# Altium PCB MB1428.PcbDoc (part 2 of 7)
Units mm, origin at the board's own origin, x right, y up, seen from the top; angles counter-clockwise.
Board outline 55.88 x 152.4 mm, 4 copper layers (Top Layer, Signal Layer 1, Signal Layer 2, Bottom Layer), stack 1.614 mm thick; 396 components, 227 nets, 1346 pads, 1469 vias.
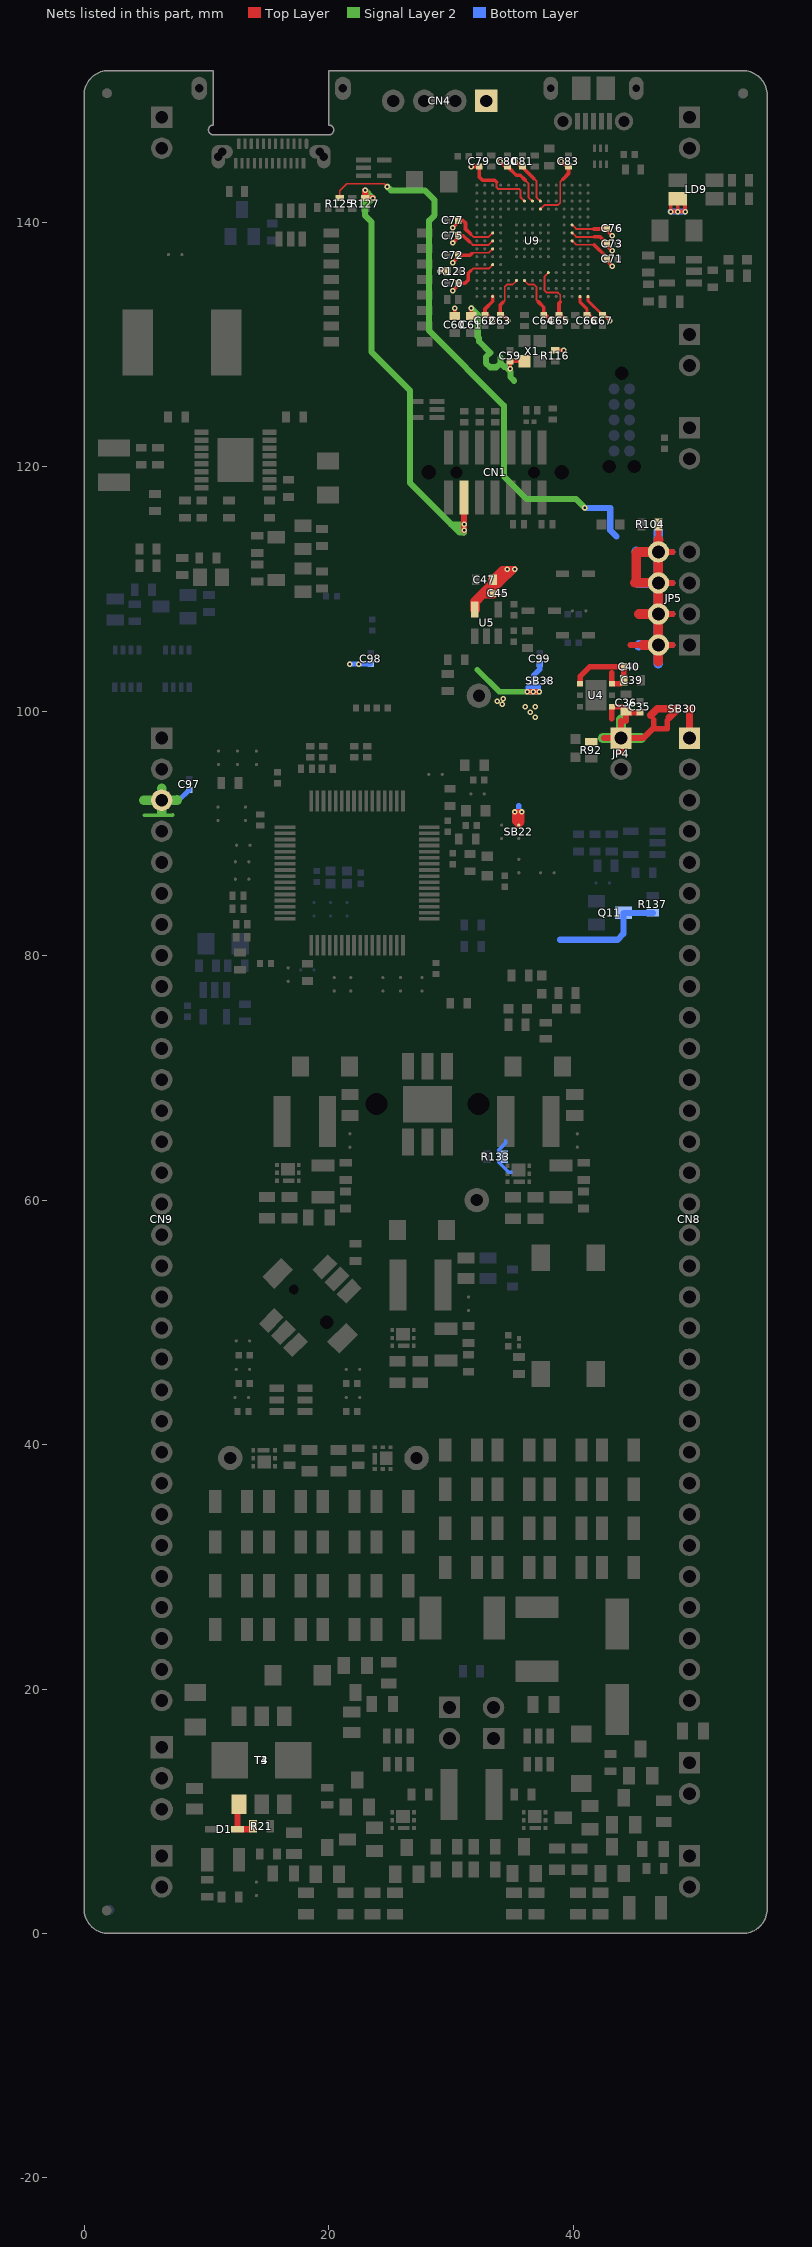
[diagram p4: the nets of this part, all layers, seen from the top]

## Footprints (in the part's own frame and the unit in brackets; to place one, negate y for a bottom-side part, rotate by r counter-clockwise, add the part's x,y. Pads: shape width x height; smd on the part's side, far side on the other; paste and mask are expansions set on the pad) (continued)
ICC_UFBGA201_176+25_10X10_P065 [mm] "IPC"
  round 0.25 smd mask+0.05: A1(-4.55,4.55) A2(-3.9,4.55) A3(-3.25,4.55) A4(-2.6,4.55) A5(-1.95,4.55) A6(-1.3,4.55) A7(-0.65,4.55) A8(0,4.55) A9(0.65,4.55) A10(1.3,4.55) A11(1.95,4.55) A12(2.6,4.55) A13(3.25,4.55) A14(3.9,4.55) A15(4.55,4.55) B1(-4.55,3.9) B2(-3.9,3.9) B3(-3.25,3.9) B4(-2.6,3.9) B5(-1.95,3.9) B6(-1.3,3.9) B7(-0.65,3.9) B8(0,3.9) B9(0.65,3.9) B10(1.3,3.9) B11(1.95,3.9) B12(2.6,3.9) B13(3.25,3.9) B14(3.9,3.9) B15(4.55,3.9) C1(-4.55,3.25) C2(-3.9,3.25) C3(-3.25,3.25) C4(-2.6,3.25) C5(-1.95,3.25) C6(-1.3,3.25) C7(-0.65,3.25) C8(0,3.25) C9(0.65,3.25) C10(1.3,3.25) C11(1.95,3.25) C12(2.6,3.25) C13(3.25,3.25) C14(3.9,3.25) C15(4.55,3.25) D1(-4.55,2.6) D2(-3.9,2.6) D3(-3.25,2.6) D4(-2.6,2.6) D5(-1.95,2.6) D6(-1.3,2.6) D7(-0.65,2.6) D8(0,2.6) D9(0.65,2.6) D10(1.3,2.6) D11(1.95,2.6) D12(2.6,2.6) D13(3.25,2.6) D14(3.9,2.6) D15(4.55,2.6) E1(-4.55,1.95) E2(-3.9,1.95) E3(-3.25,1.95) E4(-2.6,1.95) E12(2.6,1.95) E13(3.25,1.95) E14(3.9,1.95) E15(4.55,1.95) F1(-4.55,1.3) F2(-3.9,1.3) F3(-3.25,1.3) F4(-2.6,1.3) F6(-1.3,1.3) F7(-0.65,1.3) F8(0,1.3) F9(0.65,1.3) F10(1.3,1.3) F12(2.6,1.3) F13(3.25,1.3) F14(3.9,1.3) F15(4.55,1.3) G1(-4.55,0.65) G2(-3.9,0.65) G3(-3.25,0.65) G4(-2.6,0.65) G6(-1.3,0.65) G7(-0.65,0.65) G8(0,0.65) G9(0.65,0.65) G10(1.3,0.65) G12(2.6,0.65) G13(3.25,0.65) G14(3.9,0.65) G15(4.55,0.65) H1(-4.55,0) H2(-3.9,0) H3(-3.25,0) H4(-2.6,0) H6(-1.3,0) H7(-0.65,0) H8(0,0) H9(0.65,0) H10(1.3,0) H12(2.6,0) H13(3.25,0) H14(3.9,0) H15(4.55,0) J1(-4.55,-0.65) J2(-3.9,-0.65) J3(-3.25,-0.65) J4(-2.6,-0.65) J6(-1.3,-0.65) J7(-0.65,-0.65) J8(0,-0.65) J9(0.65,-0.65) J10(1.3,-0.65) J12(2.6,-0.65) J13(3.25,-0.65) J14(3.9,-0.65) J15(4.55,-0.65) K1(-4.55,-1.3) K2(-3.9,-1.3) K3(-3.25,-1.3) K4(-2.6,-1.3) K6(-1.3,-1.3) K7(-0.65,-1.3) K8(0,-1.3) K9(0.65,-1.3) K10(1.3,-1.3) K12(2.6,-1.3) K13(3.25,-1.3) K14(3.9,-1.3) K15(4.55,-1.3) L1(-4.55,-1.95) L2(-3.9,-1.95) L3(-3.25,-1.95) L4(-2.6,-1.95) L12(2.6,-1.95) L13(3.25,-1.95) L14(3.9,-1.95) L15(4.55,-1.95) M1(-4.55,-2.6) M2(-3.9,-2.6) M3(-3.25,-2.6) M4(-2.6,-2.6) M5(-1.95,-2.6) M6(-1.3,-2.6) M7(-0.65,-2.6) M8(0,-2.6) M9(0.65,-2.6) M10(1.3,-2.6) M11(1.95,-2.6) M12(2.6,-2.6) M13(3.25,-2.6) M14(3.9,-2.6) M15(4.55,-2.6) N1(-4.55,-3.25) N2(-3.9,-3.25) N3(-3.25,-3.25) N4(-2.6,-3.25) N5(-1.95,-3.25) N6(-1.3,-3.25) N7(-0.65,-3.25) N8(0,-3.25) N9(0.65,-3.25) N10(1.3,-3.25) N11(1.95,-3.25) N12(2.6,-3.25) N13(3.25,-3.25) N14(3.9,-3.25) N15(4.55,-3.25) P1(-4.55,-3.9) P2(-3.9,-3.9) P3(-3.25,-3.9) P4(-2.6,-3.9) P5(-1.95,-3.9) P6(-1.3,-3.9) P7(-0.65,-3.9) P8(0,-3.9) P9(0.65,-3.9) P10(1.3,-3.9) P11(1.95,-3.9) P12(2.6,-3.9) P13(3.25,-3.9) P14(3.9,-3.9) P15(4.55,-3.9) R1(-4.55,-4.55) R2(-3.9,-4.55) R3(-3.25,-4.55) R4(-2.6,-4.55) R5(-1.95,-4.55) R6(-1.3,-4.55) R7(-0.65,-4.55) R8(0,-4.55) R9(0.65,-4.55) R10(1.3,-4.55) R11(1.95,-4.55) R12(2.6,-4.55) R13(3.25,-4.55) R14(3.9,-4.55) R15(4.55,-4.55)
  silkscreen extent -5.22,-5.07 5.07,5.23, body extent -5.07,-5.07 5.07,5.07, height 0.61
IND_8040_WURTH_74437358068 [mm] "MCD-01372"
  rect 2.5x5.4 smd mask+0.05: 1(-3.625,0) 2(3.625,0)
  silkscreen extent -4.6,-4.25 4.6,4.25, body extent -4.6,-4.25 4.6,4.25, height 4
IND_SUNLORD_SWPA5040S [mm] "MCD-01734"
  rect 4.2x1.4 smd mask+0.05: 1(0,1.85) 2(0,-1.85)
  silkscreen extent -2.6,-2.68 2.6,2.68, body extent -2.6,-2.6 2.6,2.6, height 4
L0603 [mm]
  rect 0.8x0.95 smd mask+0.05: 1(-0.8,0) 2(0.8,0)
  silkscreen extent -1.33,-0.6 1.33,0.6, body extent -0.87,-0.47 0.87,0.47, height 0.95
LED_0603_GREEN [mm]
  rect 0.8x0.8 smd mask+0.05: 1(-0.75,0) 2(0.75,0)
  silkscreen extent -0.25,-0.4 1.25,0.4, body extent -0.8,-0.4 0.8,0.4, height 0.6
LED_0603_ORANGE_H0P4 [mm]
  rect 0.8x0.8 smd mask+0.05: 1(-0.75,0) 2(0.75,0)
  silkscreen extent -0.25,-0.4 1.25,0.4, body extent -0.8,-0.4 0.79,0.4, height 0.4
LED_0603_RED [mm]
  rect 0.8x0.8 smd mask+0.05: 1(-0.75,0) 2(0.75,0)
  silkscreen extent -0.25,-0.4 1.25,0.4, body extent -0.8,-0.4 0.8,0.4, height 0.6
LED_0603_SMD-B_BLUE_H0P4 [mm]
  rect 0.6x1 smd mask+0.05: 1(-0.65,0) 2(0.65,0)
  silkscreen extent -0.23,-0.45 1.07,0.45, body extent -0.85,-0.45 0.85,0.45, height 0.5
LED_BI-GR_HSMF-A201-A00J1 [mm] "MCD-00051"
  rect 1.1x1.5 smd mask+0.05: 1(-0.75,-1.5) 2(-0.75,1.5) 3(0.75,1.5) 4(0.75,-1.5)
  silkscreen extent -1.65,-1.85 1.5,1.7, body extent -1.5,-1.85 1.5,1.85, height 2.1
LED_PLCC6-EPAD_LUMEX_SML-LX5050SIUPGUBC [mm] "MCD-01580"
  rect 2.2x1 smd mask+0.05: 1(3.1,-1.6) 2(3.1,0) 3(3.1,1.6) 4(-3.1,1.6) 5(-3.1,0) 6(-3.1,-1.6)
  rect 3x4 smd mask+0.05: 7(0,0)
  silkscreen extent -2.5,-2.5 3.2,2.5, body extent -2.5,-2.5 2.5,2.5, height 1.35
LIGHT_10MM-SQUARE-LIGHT-BAR_LUMEX_LPB-S01110101S [mm] "MCD-01191"
  round 0 hole 1.8 slot 3.8 at 90 deg unplated mask+0.05: NPTH1(-4.18,0) NPTH2(4.18,0)
  Bottom Layer keep-out region: -5.2,1.075 -5.2,-1.075 -5.75,-1.075 -5.75,-1.05 -5.75,1.075
  Bottom Layer keep-out region: 5.2,-1.075 5.2,1.075 5.75,1.075 5.75,1.05 5.75,-1.075
  silkscreen extent -5.08,-5.08 5.08,5.08, body extent -5.08,-5.08 5.08,5.08, height 10.3
LOGO_ETIQUETTE [mm]
  silkscreen extent 0,0 27,10
MIRE_PLACE_SMD_0P8MM [mm]
  round 0.8 smd paste-10 mask+0.2: 1(0,0)
  Top Layer keep-out circle w0.01: c0,0 r0.804
MOS_POWERFLAT_2X2_P065 [mm] "MCD-01028  PowerFLAT, 6-Leads, Body 2.1x2.1mm"
  rect 0.35x0.3 smd mask+0.038: 1(-0.65,-0.9) 2(0,-0.9) 3(0.65,-0.9) 4(0.65,0.875) 5(0,0.875) 6(-0.65,0.875)
  rect 0.35x0.95 smd mask+0.038: 7(0.65,0.05)
  rect 1.05x1.125 smd mask+0.038: 8(-0.3,-0.012)
  silkscreen extent -1.2,-1.2 1.05,1.05, body extent -1.05,-1.05 1.05,1.05, height 0.81
MOS_POWERFLAT_3P3X3P3_P065 [mm] "MCD-01126"
  rect 0.4x0.75 smd mask+0.05: 1(-0.975,-1.525) 2(-0.325,-1.525) 3(0.325,-1.525) 4(0.975,-1.525) 6(0.325,1.525) 7(-0.325,1.525)
  rect 0.45x0.75 smd mask+0.05: 5(1,1.525) 8(-1,1.525)
  Top Layer region: -1.755,0.2 -1.755,-0.2 -1.225,-0.2 -1.225,-0.5 1.225,-0.5 1.225,-0.2 1.755,-0.2 1.755,0.2 1.225,0.2 1.225,1.9 -1.225,1.9 -1.225,0.2
  silkscreen extent -1.63,-1.55 1.63,1.55, body extent -1.75,-1.75 1.75,1.75, height 0.91
MOS_SOT23 [mm]
  rect 1x1.4 smd mask+0.05: 1(-0.95,-1.1) 2(0.95,-1.1) 3(0,1.1)
  silkscreen extent -1.63,-0.82 1.63,0.82, body extent -1.56,-1.25 1.56,1.25, height 1.1
MOS_SOT23-5L [mm]
  rect 0.6x1.3 smd mask+0.05: 1(-0.95,-1.1) 2(0,-1.1) 3(0.95,-1.1) 4(0.95,1.1) 5(-0.95,1.1)
  silkscreen extent -1.6,-0.95 1.6,0.97, body extent -1.52,-1.25 1.52,1.25, height 1.45
MOS_SOT23-6L [mm]
  rect 0.6x1.2 smd mask+0.05: 1(-0.95,-1.15) 2(0,-1.15) 3(0.95,-1.15) 4(0.95,1.15) 5(0,1.15) 6(-0.95,1.15)
  silkscreen extent -1.53,-0.87 1.53,0.87, body extent -1.52,-1.5 1.52,1.5, height 1.3
NPN_SOT23 [mm]
  rect 1x1.4 smd mask+0.05: 1(-0.95,-1.1) 2(0.95,-1.1) 3(0,1.1)
  silkscreen extent -1.63,-0.82 1.63,0.82, body extent -1.56,-1.25 1.56,1.25, height 1.1
OSC_NDK_NZ2520SB_4P [mm]
  rect 1x1 smd mask+0.05: 1(-0.825,-0.625) 2(0.825,-0.625) 3(0.825,0.625) 4(-0.825,0.625)
  silkscreen extent -1.43,-1.22 1.2,1.05, body extent -1.3,-1.05 1.3,1.05, height 0.91
PTC_EATON_FUSE_PTS1812_H0P9 [mm] "MCD-01682"
  rect 1.78x3.5 smd mask+0.05: 1(-2.615,0) 2(2.615,0)
  silkscreen extent -1.6,-1.73 1.6,1.73, body extent -2.36,-1.74 2.37,1.74, height 1.03
R0402 [mm]
  rect 0.51x0.7 smd mask+0.05: 1(-0.45,0) 2(0.45,0)
  silkscreen extent 0,-0.3 0,0.3, body extent -0.52,-0.3 0.52,0.3, height 0.4
R0603 [mm]
  rect 0.64x1 smd mask+0.05: 1(-0.7,0) 2(0.7,0)
  silkscreen extent -1.05,-0.58 1.05,0.58, body extent -0.9,-0.5 0.9,0.5, height 0.56
R0603_H0P45 [mm]
  rect 0.64x1 smd mask+0.05: 1(-0.7,0) 2(0.7,0)
  silkscreen extent -1.05,-0.58 1.05,0.58, body extent -0.9,-0.5 0.9,0.5, height 0.56
R0805 [mm]
  rect 0.85x1.3 smd mask+0.05: 1(-0.875,0) 2(0.875,0)
  silkscreen extent -0.33,-0.67 0.33,0.67, body extent -1.05,-0.68 1.05,0.68, height 0.65
R0805_H0P5 [mm] "MCD-01537"
  rect 0.85x1.3 smd mask+0.05: 1(-0.875,0) 2(0.875,0)
  silkscreen extent -0.33,-0.67 0.33,0.67, body extent -1.05,-0.68 1.05,0.68, height 0.6
R1206_H0P55 [mm]
  rect 1x1.9 smd mask+0.05: 1(-1.3,0) 2(1.3,0)
  silkscreen extent -0.67,-0.85 0.67,0.85, body extent -1.6,-0.85 1.6,0.85, height 0.65
REG_SOT23-5L [mm]
  rect 0.6x1.3 smd mask+0.05: 1(-0.95,-1.1) 2(0,-1.1) 3(0.95,-1.1) 4(0.95,1.1) 5(-0.95,1.1)
  silkscreen extent -1.6,-0.95 1.6,0.97, body extent -1.52,-1.25 1.52,1.25, height 1.1
Sheetbox_4L2S [mil] "Sheetbox 4 layers / 2 silkscreens"
  round 20 on Mech16: 1(813.78,210.69) 1(2736.9,210.69)
SOLDER-BRIDGE_R0603-0R [mil]
  round 10 smd paste-393.7: 1(-19.69,0) 2(23.62,0)
  Top Layer region: -5.91,19.69 13.78,0 -5.91,-19.68 47.24,-19.68 47.24,19.69 -5.91,19.69
  Top Layer region: -47.24,-19.68 -47.24,19.69 -15.75,19.69 3.94,0 -15.75,-19.68 -47.24,-19.68
  silkscreen extent -50,-23 50,23, body extent -36,-20 36,20, height 22
SWI_C&K_TDP08H1SBD1 [mm] "MCD-01684"
  rect 0.76x1.27 smd mask+0.05: 1(-4.445,-3.81) 2(-3.175,-3.81) 3(-1.905,-3.81) 4(-0.635,-3.81) 5(0.635,-3.81) 6(1.905,-3.81) 7(3.175,-3.81) 8(4.445,-3.81) 9(-4.445,3.81) 10(-3.175,3.81) 11(-1.905,3.81) 12(-0.635,3.81) 13(0.635,3.81) 14(1.905,3.81) 15(3.175,3.81) 16(4.445,3.81)
  silkscreen extent -5.65,-3 5.65,3, body extent -5.65,-4.06 5.65,4.06, height 4.4
SWI_WEALTHMETAL_TD-0341_4P_BLACK [mm]
  rect 1.52x2.16 smd mask+0.05: 1(-2.25,-4.75) 2(-2.25,4.75) 3(2.25,-4.75) 4(2.25,4.75)
  silkscreen extent -3,-3.5 3,3.5, body extent -3,-5.15 3,5.15, height 7.55
SWI_XIEJIA_MT-008A_6P [mm] "MCD-00132"
  rect 1.8x1.1 smd mask+0.05: 1(-3.1,1.4) 2(-3.1,0) 3(-3.1,-1.4) 4(3.1,1.4) 5(3.1,0) 6(3.1,-1.4)
  rect 2.2x1.4 smd mask+0.05: 7(0,3.75) 8(0,-3.75)
  round 0 hole 0.8 unplated paste-10 mask+0.05: NPTH1(0,1.9)
  round 0 hole 1.1 unplated paste-10 mask+0.05: NPTH2(0,-1.9)
  silkscreen extent -3.7,-3.7 3.7,3.7, body extent -3.85,-3.75 3.85,3.75, height 5.2
TP_PTH_1MM_2MM [mm] "MCD-01506"
  round 2 hole 1 mask+0.05: 1(0,0)
  silkscreen extent -1.2,-1.2 1.2,1.2
TRS_WURTH_749251125 [mm] "MCD-01570"
  rect 1.6x1.2 smd mask+0.05: 1(-3.6,1.85) 2(-3.6,0) 3(-3.6,-1.85) 4(3.6,-1.85) 5(3.6,0) 6(3.6,1.85)
  rect 3x2.5 smd mask+0.05: 7(0,-2.6) 8(0,2.6)
  silkscreen extent -3,-3 3,3, body extent -3.85,-3.45 3.85,3.45, height 5.33
TRS_WURTH_750317809 [mm] "MCD-01596"
  rect 1.6x1.2 smd mask+0.05: 1(-3.6,1.85) 2(-3.6,0) 3(-3.6,-1.85) 4(3.6,-1.85) 5(3.6,0) 6(3.6,1.85)
  rect 3x3 smd mask+0.05: 7(0,-2.6) 8(0,2.6)
  silkscreen extent -3,-3 3,3, body extent -3.85,-3.45 3.85,3.45, height 5.33

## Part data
B1: library part MCD-00001, "Non-Open Push-Button 0.1A 24V BLACK", Manufacturer=WEALTHMETAL, Manufacturer_Part_Number=TD-0341
B2: library part MCD-00132, "Joystick, 4 dir, 1 OK", Manufacturer="XIEJIA Electronics", Manufacturer_Part_Number=MT-008A
C1: library part MCD-01576, "Capacitor, MLCC, 680pF, 16V, X7R, 10%, 0603, T=0.8mm", Manufacturer=YAGEO, Manufacturer_Part_Number=CC0603KRX7R7BB681, Package=C0603
C2: library part MCD-01544, "Capacitor, MLCC, 6.8nF, 50V, X7R, 10%, 0603, T=0.8mm", Manufacturer=YAGEO, Manufacturer_Part_Number=CC0603KRX7R9BB682, Package=C0603
C3: library part MCD-01103, "Capacitor,22nF,50V,X7R,10%,0603", Manufacturer=YAGEO, Manufacturer_Part_Number=CC0603KRX7R9BB223, Package=C0603
C4 C5 C6 C9 C87: library part MCD-01525, "Capacitor, MLCC, 100nF, 50V, X7R, 10%, 0805, T=0,85mm", Manufacturer=YAGEO, Manufacturer_Part_Number=CC0805KRX7R9BB104, Package=C0805
C7: library part MCD-01683, "Capacitor, Electrolytic, 100µF, 35V, 20%, SMT, D=8mm, T=10.5mm", Manufacturer="WURTH ELEKTRONIK", Manufacturer_Part_Number=865060553006
C8: library part MCD-01517, "Capacitor, MLCC, 47uF, 25V, X5R, 20%, 1206, T=1,6mm", Manufacturer=TDK, Manufacturer_Part_Number=C3216X5R1E476M160AC, Package=C1206
C10 C11 C12 C13 C15 C16 C24 C25 C26 C28 C30 C31 C33 C34 C35 C40 C43 C45 C56 C59 C62 C63 C64 C65 C66 C67 C70 C71 C72 C73 C75 C76 C77 C79 C80 C81 C83 C88 C97 C98 C99 C100 C101 C103 C104: library part MCD-00102, "Capacitor, MLCC, 100nF, 16V, X7R, 10%, 0402, T=0,5mm", Alternate_Manufacturer=MURATA, Alternate_Manufacturer_Part_Number=GCM155R71C104KA55D, Manufacturer=YAGEO, Manufacturer_Part_Number=CC0402KRX7R7BB104, Package=C0402
C14 C18 C19 C22 C90 C91: library part MCD-01731, "Capacitor, MLCC, 470pF, 100V, X7R, 10%, 0603, T=0.8mm", Manufacturer=YAGEO, Manufacturer_Part_Number=CC0603KRX7R0BB471, Package=C0603
C17 C20 C21: library part MCD-01550, "Capacitor, MLCC, 1uF, 16V, X5R, 10%, 0805, T=0.85mm", Manufacturer=YAGEO, Manufacturer_Part_Number=CC0805KRX5R7BB105, Package=C0805
C23 C29 C36 C39 C42 C47 C55 C61 C68 C69: library part MCD-00010, "Capacitor, MLCC, 1uF, 16V, X5R, 10%, 0603, T=0,8mm", Manufacturer=YAGEO, Manufacturer_Part_Number=CC0603KRX5R7BB105, Package=C0603
C27 C96: library part MCD-01124, "Capacitor, MLCC, 10µF, 10V, X5R, 10%, 0603, T=0.8mm", Manufacturer=MURATA, Manufacturer_Part_Number=GRM188R61A106KAAL, Package=C0603
C32 C51 C60 C86: library part MCD-00009, "Capacitor, MLCC, 4.7uF, 16V, X5R, 10%, 0603, T=0.8mm", Manufacturer=YAGEO, Manufacturer_Part_Number=CC0603KRX5R7BB475, Package=C0603
C37 C38: library part MCD-01597, "Capacitor, MLCC, 390pF, 50V, NPO, 5%, 0402, T=0,5mm", Manufacturer=YAGEO, Manufacturer_Part_Number=CC0402JRNPO9BN391, Package=C0402
C41 C49: library part MCD-01007, "Capacitor, MLCC, 10nF, 16V, X7R, 10%, 0603, T=0.8mm", Manufacturer=YAGEO, Manufacturer_Part_Number=CC0603KRX7R7BB103, Package=C0603
C44: library part MCD-00011, "Capacitor, MLCC, 10nF, 16V, X7R, 10%, 0402, T=0.5mm", Manufacturer=YAGEO, Manufacturer_Part_Number=CC0402KRX7R7BB103, Package=C0402
C46: library part MCD-01719, "Capacitor, MLCC, 27nF, 25V, C0G, 5%, 0805, T=1.1mm", Manufacturer=KEMET, Manufacturer_Part_Number=C0805C273J3GACTU, Package=C0805
C48: library part MCD-00637, "Capacitor, MLCC, 10pF, 50V, NPO, 5%, 0603, T=0,8mm", Manufacturer=YAGEO, Manufacturer_Part_Number=CC0603JRNPO9BN100, Package=C0603
C50: library part MCD-01923, "Capacitor, MLCC, 2.7nF, 16V, NPO, 5%, 0603, T=0,8mm", Manufacturer=YAGEO, Manufacturer_Part_Number=CC0603JRNPO7BN272, Package=C0603
C52: library part MCD-01559, "Capacitor, MLCC, 6.8uF, 50V, X5R, 10%, 1206, T=1.6mm", Manufacturer=TDK, Manufacturer_Part_Number=C3216X5R1H685K160AB, Package=C1206
C53: library part MCD-01703, "Capacitor,1uF,50V,X5R,10%,0603, T=0.8mm", Manufacturer=YAGEO, Manufacturer_Part_Number=CC0603KRX5R9BB105, Package=C0603
C54: library part MCD-00614, "Capacitor, MLCC, 22uF, 16V, 1210, X7R, 20%, T=2,5mm, ESR 2mohm@410KHz", Manufacturer=MURATA, Manufacturer_Part_Number=GCM32ER71C226ME19, Package=C1210
C57 C58: library part MCD-01667, "Capacitor, MLCC, 68nF, 50V, X7R, 10%, 0603, T=0.8mm", Manufacturer=YAGEO, Manufacturer_Part_Number=CC0603KRX7R9BB683, Package=C0603
C74 C78: library part MCD-00008, "Capacitor, MLCC, 2.2uF, 16V, X7R, 10%, 1206, T=1,15mm", Alternate_Manufacturer=KEMET, Alternate_Manufacturer_Part_Number=C1206C225K4RAC, Manufacturer=YAGEO, Manufacturer_Part_Number=CC1206KKX7R7BB225, Package=C1206
C82: library part MCD-00012, "Capacitor, MLCC, 2.2uF, 10V, X5R, 10%, 0603, T=0,8mm", Alternate_Manufacturer=KEMET, Alternate_Manufacturer_Part_Number=C0603C225K8PACTU, Manufacturer=YAGEO, Manufacturer_Part_Number=CC0603KRX5R6BB225, Package=C0603
C84: library part MCD-00016, "Capacitor, MLCC, 20pF, 50V, NPO, 5%, 0402, T=0,5mm", Manufacturer=YAGEO, Manufacturer_Part_Number=CC0402JRNPO9BN200, Package=C0402
C85: library part MCD-00205, "Capacitor, MLCC, 100pF, 50V, NPO, 5%, 0402, T=0,5mm", Manufacturer=YAGEO, Manufacturer_Part_Number=CC0402JRNPO9BN101, Package=C0402
C89: library part MCD-01184, "Capacitor, COG, 22nF,50V, X7S, 5%, 1206, T=0.85mm", Manufacturer=MURATA, Manufacturer_Part_Number=GRM3195C1H223JA01L, Package=C1206
C92 C93: library part MCD-00674, "Capacitor, MLCC, 6.8pF, 50V, NPO, +-0.25pF, 0402, T=0.5mm", Manufacturer=YAGEO, Manufacturer_Part_Number=CC0402CRNPO9BN6R8, Package=C0402
C94: library part MCD-01648, "Capacitor, MLCC, 100pF, 50V, NPO, 5%, 0603, T=0,8mm", Manufacturer=YAGEO, Manufacturer_Part_Number=CC0603JRNPO9BN101, Package=C0603
C95: library part MCD-00211, "Capacitor, MLCC, 100nF, 16V, X7R, 10%, 0603, T=0,8mm", Manufacturer=YAGEO, Manufacturer_Part_Number=CC0603KRX7R7BB104, Package=C0603
C102: library part MCD-01549, "Capacitor, MLCC, 1nF, 50V, X7R,10%, 0805, T=0,6mm", Manufacturer=YAGEO, Manufacturer_Part_Number=CC0805KRX7R9BB102, Package=C0805
C105: library part MCD-01099, "Capacitor,100nF,50V,X7R,10%,0603", Manufacturer=YAGEO, Manufacturer_Part_Number=CC0603KRX7R9BB104, Package=C0603
CN1: library part MCD-00592, "Header 7x2, 1.27mm, Dual row, Straight, \"STDC14_MEDIUM\" : footprint compatible with FTSH-107-01-L-DV,-K,-A,-P,-ES (use \"STDC14_BIG\" to also be compatible with SHF-107-01-L-D-SM,-K)", Manufacturer=SAMTEC, Manufacturer_Part_Number=FTSH-107-01-L-DV-K
CN2: library part MCD-01679, "USB Type C certified Connector SMT Mid-mount", Manufacturer="LITKCON TECHNOLOGY", Manufacturer_Part_Number=CNG008S130R
CN3: library part MCD-00028, "USB-MICRO-B, 0.65mm, RA, SMT, Bottom Mount,", Manufacturer=MOLEX, Manufacturer_Part_Number=1050170001
CN4: library part MCD-00029, "Header, 4x1, 2,54mm, VR, TH, Height 5.84mm/2.54mm", Manufacturer=SAMTEC, Manufacturer_Part_Number=TSW-104-07-x-S
CN5 CN6 CN11 CN12: library part MCD-01668, "Header 2x1, 2.54mm, VR, TH, height 5.84mm/5.08 mm, height total 13.46 mm", Manufacturer=LYCONN, Manufacturer_Part_Number=313102S141346
CN7: library part MCD-01855, "Header 2x1, 2.54mm, VR, TH, height 5.84mm/7.50 mm, height total 15.84 mm", Manufacturer=LYCONN, Manufacturer_Part_Number=313102S1411584
CN8 CN9: library part MCD-01728, "'Header 32x1, 2.54mm, VR, TH, height 5.84mm/5.08 mm, height total 13.46 mm", Manufacturer=LYCONN, Manufacturer_Part_Number=313132S141346
CN10: library part MCD-00031, "Tag_Connector Header, 10x2, No legs", Manufacturer="TAG-CONNECT LLC", Manufacturer_Part_Number=TC2050-IDC-NL-FP
D1: library part MCD-01880, "ultrafast and RF switching diode, VF = 0.41 V @ IF = 1mA; VR = 70V;", Manufacturer=STMICROELECTRONICS, Manufacturer_Part_Number=BAS70JFILM, Package=SOD-323
D2 D4: library part MCD-01524, "Single surface mount small signal schotky diode", Manufacturer=STMICROELECTRONICS, Manufacturer_Part_Number=BAT54FILM, Package=SOT-23
D3 D5: library part MCD-01522, "Transil unidirectional diode Vrm=15V, Vbr=16.7V(1mA), Vcl=32.5V(71A), SMA", Manufacturer=STMICROELECTRONICS, Manufacturer_Part_Number=SMAJ15A-TR, Package=SMA
D6 D7 D8: library part MCD-00606, "Low Drop power Schottky rectifier(1A, 40V, 0.37 V)", Manufacturer=STMICROELECTRONICS, Manufacturer_Part_Number=STPS1L40AY, Package=SMA
D9 D10 D11: library part MCD-00034, "BAT60JFILM", Manufacturer=STMICROELECTRONICS
F1 F2: library part MCD-01682, "SMD, PTC resettable fuse, IH:0.2A, IT:0.4A, Vdc_max:30V, Rmax:5 ohm", Manufacturer=EATON, Manufacturer_Part_Number=PTS181230V020
JP1: library part MCD-00684, "Header, 3x1, 2,54mm, VR, TH, Height 5.84mm/2.54mm - Shunt Fitted 1-2 by default", Manufacturer=SAMTEC, Manufacturer_Part_Number=TSW-103-07-F-S
JP2 JP3 JP6: library part MCD-01660, "Header 2x1, 2.54mm, VR, TH, height 6 mm / 3 mm, total 11.6mm - Shunt not Fitted by default", Manufacturer=JIUBABA, Manufacturer_Part_Number=313102S111116
JP4 JP7: library part MCD-01662, "Header 2x1, 2.54mm, VR, TH, height 6 mm / 3 mm, total 11.6mm - Shunt Fitted by default", Manufacturer=JIUBABA, Manufacturer_Part_Number=313102S111116
JP5: library part MCD-01661, "Header, 4x2, 2,54mm, VR, TH, Height 6mm/3m, total 11.6mm - Shunt Fitted 1-2", Manufacturer=JIUBABA, Manufacturer_Part_Number=313208S141116
L1: library part MCD-01787, "SMD Wire wound power inductor, 51uH, 20%, Isat 1.2A, 380mohm, 5.0x5.0x4.0mm", Manufacturer=SUNLORD, Manufacturer_Part_Number=SWPA5040S510MT
L2 L3 L4: library part MCD-01734, "SMD Wire wound power inductor, 100uH, 20%, Isat 0.9A, 560mohm, 5.0x5.0x4.0mm", Manufacturer=SUNLORD, Manufacturer_Part_Number=SWPA5040S101MT
L5 L6: library part MCD-01735, "Bead,300R,500mA,0603", Manufacturer=TAI-TECH, Manufacturer_Part_Number=FCM1608KF-301T05, Package=L0603
L7: library part MCD-00047, "SMD Chip ferrite bead, 600R@100MHz +/-25%, 350mA, 500mohm DC, 0603, T=0.8mm", Manufacturer=TAI-TECH, Manufacturer_Part_Number=FCM1608KF-601T03
L8: library part MCD-01372, "Inductor 6.8µH +/-20% Isat= 13.5A DCR=33.40 mOhm", Manufacturer=WURTH, Manufacturer_Part_Number="744 373 580 68", Package=WE-LHMI_SMD_8040
LD1: library part MCD-01580, "Mid Power RGB LED , SMD, 3x150 mA", Manufacturer=LUMEX, Manufacturer_Part_Number=SML-LX5050SIUPGUBC
LD2: library part MCD-01131, "LED Blue, 0603 SMD, Forward Voltage Min=2,8V, Max=3,1V", Manufacturer=EVERLIGHT, Manufacturer_Part_Number=19-217-BHC-ZL1M2RY-3T, Package=0603
LD3: library part MCD-00321, "LED, Orange, 0603", Manufacturer=EVERLIGHT, Manufacturer_Part_Number=19-217/S2C-AM2N2VY/3T, Package="LED 0603"
LD4 LD6 LD7: library part MCD-00050, "LED, Green, 0603", Manufacturer=EVERLIGHT, Manufacturer_Part_Number=19-213SYGC/S530-E2/TR8, Package="LED 0603"
LD5 LD8: library part MCD-00049, "LED, Red, 0603", Manufacturer=EVERLIGHT, Manufacturer_Part_Number=19-213-R6C-AP1Q2B/3T, Package="LED 0603"
LD9: library part MCD-00051, "LED Bicolor", Alternate_Manufacturer=EVERLUCK, Alternate_Manufacturer_Part_Number=LE-RGW35280, Manufacturer="AVAGO TECHNOLOGIES", Manufacturer_Part_Number=HSMF-A201-A00J1
LPB1: library part MCD-01191, "10mm Square Light Bar.", Alternate_Manufacturer=LUMEX, Alternate_Manufacturer_Part_Number=LPB-S01110101S-110945
Q1 Q2 Q3 Q4: library part MCD-01518, "MOSFET, Single N-Channel , Vgs(th): 2.5V, Id: 280mA, Vds(max): 60V, Vgs(max): +/-20V, Rdson:3 ohm@Vgs=5V", Alternate_Manufacturer=FAIRCHILD, Alternate_Manufacturer_Part_Number=NDS7002A, Manufacturer="ON SEMICONDUCTOR", Package=SOT23-3L
Q5 Q6: library part MCD-01527, "Transistor Bipolar PNP, 45V, 500mA, 100MHz, 300mW, SOT23-3", Alternate_Manufacturer=NXP, Alternate_Manufacturer_Part_Number=BC807, Manufacturer=NEXPERIA, Package=PNP_SOT23
Q7 Q8: library part MCD-01526, "Transistor Bipolar NPN, 45V, 500mA, 100MHz, 300mW, SOT23-3", Alternate_Manufacturer=NXP, Alternate_Manufacturer_Part_Number=BC817, Manufacturer=NEXPERIA, Package=SOT23-3
Q9 Q10 Q14: library part MCD-00151, "N-channel enhancement mode field-effect transistor", Manufacturer=NXP, Manufacturer_Part_Number=BSN20
Q11: library part MCD-01737, "NPN Bipolar Transistor", Manufacturer="ON SEMICONDUCTOR", Manufacturer_Part_Number=MMBT2222ALT1G
Q12 Q13: library part MCD-01126, "Power Mosfet, P-channel,VDS -30V,RDS 12mohm typ,ID -9A", Manufacturer=STMICROELECTRONICS, Manufacturer_Part_Number=STL9P3LLH6, Package="PowerFLAT 3.3x3.3"
R1 R7 R12 R13 R66 R71 R73: library part MCD-01154, "Resistor,10K,0805,1%,1/8W", Manufacturer=YAGEO, Manufacturer_Part_Number=RC0805FR-0710KL, Package=R0805
R2 R8 R15 R19 R20 R28 R57 R58 R65 R72 R74 R75: library part MCD-01548, "Resistor,10R,0805,1%, 1/8W", Manufacturer=YAGEO, Manufacturer_Part_Number=RC0805FR-0710RL, Package=R0805
R3 R4 R5 R6: library part MCD-01537, "Resistor,270R,0805,1%,1/8W", Manufacturer=YAGEO, Manufacturer_Part_Number=RC0805FR-07270RL, Package=R0805
R9: library part MCD-01546, "Resistor, 1R, 1206, 0.1%, 1/4W", Manufacturer=YAGEO, Manufacturer_Part_Number=RT1206BRD071RL, Package=R1206
R10: library part MCD-00056, "Resistor,0R,0603,5%,1/10W", Manufacturer=YAGEO, Manufacturer_Part_Number=RC0603JR-070RL, Package=R0603
R11: library part MCD-01654, "Resistor, 6K8, 0805, 0.1%, 1/8W, 50ppm", Manufacturer=VIKING, Manufacturer_Part_Number=AR05BTD6801, Package=R0805
R14 R27: library part MCD-01547, "Resistor,47R,0805,1%,1/8W", Manufacturer=YAGEO, Manufacturer_Part_Number=RC0805FR-0747RL, Package=R0805
R16: library part MCD-01881, "Resistor,187R,1206,1%,1/4W", Manufacturer=YAGEO, Manufacturer_Part_Number=RC1206FR-07187RL, Package=R1206
R17: library part MCD-01652, "Resistor, 27K, 0805, 0.1%, 1/8W, 50ppm", Manufacturer=VIKING, Manufacturer_Part_Number=AR05BTD2702, Package=R0805
R18: library part MCD-01653, "Resistor, 3K3, 0805, 0.1%, 1/8W, 50ppm", Manufacturer=VIKING, Manufacturer_Part_Number=AR05BTD3301, Package=R0805
R21: library part MCD-01882, "Resistor,5K1,0603,1%,1/10W", Manufacturer=YAGEO, Manufacturer_Part_Number=RC0603FR-075K1L, Package=R0603
R22: library part MCD-01649, "Resistor, 13K3, 0805, 0.1%, 1/8W, 50ppm", Manufacturer=VIKING, Manufacturer_Part_Number=AR05BTD1332, Package=R0805
R23 R26 R80 R82 R121: library part MCD-00070, "Resistor,1K,0603,1%,1/10W", Manufacturer=YAGEO, Manufacturer_Part_Number=RC0603FR-071KL, Package=R0603
R24 R25 R132 R133: library part MCD-00181, "Resistor,0R,0603,ULO", Manufacturer=ROHM, Manufacturer_Part_Number=PMR03EZPJ000, Package=R0603
R29 R30 R31 R32 R33 R34 R35 R36 R37 R38 R39 R40 R41 R42 R43 R44 R45 R46 R47 R48 R49 R50 R51 R52 R53 R54 R55 R56 R61 R62 R63 R64: library part MCD-01681, "Resistor,33R,1206,1%,1/4W", Manufacturer=YAGEO, Manufacturer_Part_Number=RC1206FR-0733RL, Package=R1206
R59 R60 R83 R98 R103 R122 R141: library part MCD-00220, "Resistor,10K,0603,1%,1/10W", Manufacturer=YAGEO, Manufacturer_Part_Number=RC0603FR-0710KL, Package=R0603
R67 R70: library part MCD-00224, "Resistor,100R,0603,1%,1/10W", Manufacturer=YAGEO, Manufacturer_Part_Number=RC0603FR-07100RL, Package=R0603
R68 R76 R77: library part MCD-01528, "Resistor, 3R01, 1206, 1%, 1/4W", Manufacturer=YAGEO, Manufacturer_Part_Number=RC1206FR-073R01L, Package=R1206
R69 R78 R79: library part MCD-00456, "Resistor,33R,0603,1%,1/10W", Manufacturer=YAGEO, Manufacturer_Part_Number=RC0603FR-0733RL, Package=R0603
R81 R92 R128 R129 R142: library part MCD-00197, "Resistor,330R,0603,1%,1/10W", Manufacturer=YAGEO, Manufacturer_Part_Number=RC0603FR-07330RL, Package=R0603
R84 R85 R86 R87 R90 R91 R93 R94 R95 R96: library part MCD-00052, "Resistor,0R,0402,5%,1/16W", Manufacturer=YAGEO, Manufacturer_Part_Number=RC0402JR-070RL, Package=R0402
R88 R105 R111 R112 R113 R114 R115: library part MCD-00481, "Resistor,47R,0402,1%,1/16W", Manufacturer=YAGEO, Manufacturer_Part_Number=RC0402FR-0747RL, Package=R0402
R89: library part MCD-00354, "Resistor,470R,0603,1%,1/10W", Manufacturer=YAGEO, Manufacturer_Part_Number=RC0603FR-07470RL, Package=R0603
R97: library part MCD-00341, "Resistor,15K,0603,1%,1/10W", Manufacturer=YAGEO, Manufacturer_Part_Number=RC0603FR-0715KL, Package=R0603
R99: library part MCD-00414, "Resistor,180K,0603,1%,1/10W", Manufacturer=YAGEO, Manufacturer_Part_Number=RC0603FR-07180KL, Package=R0603
R100: library part MCD-01571, "Resistor, 4K22, 0603, 1%, 1/10W", Manufacturer=YAGEO, Manufacturer_Part_Number=RC0603FR-074K22L, Package=R0603
R101: library part MCD-01793, "Resistor, 64.9K, 0603, 1%, 1/10W", Manufacturer=YAGEO, Manufacturer_Part_Number=RC0603FR-0764K9L, Package=R0603
R102: library part MCD-01794, "Resistor, 59K, 0603, 1%, 1/10W", Manufacturer=YAGEO, Manufacturer_Part_Number=RC0603FR-0759KL, Package=R0603
R104: library part MCD-00528, "Resistor,820R,0603,1%,1/10W", Manufacturer=YAGEO, Manufacturer_Part_Number=RC0603FR-07820RL, Package=R0603
R106 R117 R130: library part MCD-00119, "Resistor,100R,0402,1%,1/16W", Manufacturer=YAGEO, Manufacturer_Part_Number=RC0402FR-07100RL, Package=R0402
R107: library part MCD-00424, "Resistor,200K,0603,1%,1/10W", Manufacturer=YAGEO, Manufacturer_Part_Number=RC0603FR-07200KL, Package=R0603
R108 R135: library part MCD-01171, "Resistor,49K9,0603,1%", Manufacturer=YAGEO, Manufacturer_Part_Number=RC0603FR-0749K9L, Package=R0603
R109: library part MCD-01568, "Resistor, 787K, 0603, 1%, 1/10W", Manufacturer=YAGEO, Manufacturer_Part_Number=RC0603FR-07787KL, Package=R0603
R110: library part MCD-01569, "Resistor, 1M05, 0603, 1%, 1/10W", Manufacturer=YAGEO, Manufacturer_Part_Number=RC0603FR-071M05L, Package=R0603
R116 R118 R120 R123: library part MCD-00053, "Resistor,10K,0402,1%,1/16W", Manufacturer=YAGEO, Manufacturer_Part_Number=RC0402FR-0710KL, Package=R0402
R119: library part MCD-00223, "Resistor,100K,0603,1%,1/10W", Manufacturer=YAGEO, Manufacturer_Part_Number=RC0603FR-07100KL, Package=R0603
R124 R126 R127: library part MCD-00065, "Resistor,4K7,0402,1%,1/16W", Alternate_Manufacturer=YAGEO, Alternate_Manufacturer_Part_Number=RT0402FRE074K7L, Manufacturer_Part_Number=RC0402FR-074K7L, Package=R0402
R125: library part MCD-00055, "Resistor,2K7,0402,1%,1/16W", Manufacturer=YAGEO, Manufacturer_Part_Number=RC0402FR-072K7L, Package=R0402
R131: library part MCD-00185, "Resistor,3K,0402,1%,1/16W", Manufacturer=YAGEO, Manufacturer_Part_Number=RC0402FR-073KL, Package=R0402
R134: library part MCD-00478, "Resistor,43K,0603,1%,1/10W", Manufacturer=YAGEO, Manufacturer_Part_Number=RC0603FR-0743KL, Package=R0603
R136: library part MCD-00458, "Resistor,330K,0603,1%,1/10W", Manufacturer=YAGEO, Manufacturer_Part_Number=RC0603FR-07330KL, Package=R0603
R137: library part MCD-00342, "Resistor,180R,0603,1%,1/10W", Manufacturer=YAGEO, Manufacturer_Part_Number=RC0603FR-07180RL, Package=R0603
R138: library part MCD-01669, "Resistor, 10K, 0603, 0.1%,1/10W", Manufacturer=PANASONIC, Manufacturer_Part_Number=ERA3AEB103V, Package=R0603
R139: library part MCD-01670, "Resistor, 33K, 0603, 0.1%,1/10W", Manufacturer=PANASONIC, Manufacturer_Part_Number=ERA3AEB333V, Package=R0603
R140: library part MCD-00494, "Resistor,56K,0603,1%,1/10W", Manufacturer=YAGEO, Manufacturer_Part_Number=RC0603FR-0756KL, Package=R0603
SB1 SB13 SB18 SB22 SB28 SB34 SB35 SB36 SB37: library part MCD-00072, "Solder Bridge OFF", Manufacturer=YAGEO, Manufacturer_Part_Number=RC0603JR-070RL, Package=SB0603
SB2 SB3 SB4 SB5 SB6 SB7 SB8 SB9 SB10 SB11 SB12 SB14 SB15 SB16 SB17 SB19 SB20 SB21 SB23 SB24 SB25 SB26 SB27 SB29 SB30 SB31 SB32 SB33 SB38: library part MCD-00071, "Solder Bridge ON", Manufacturer=YAGEO, Manufacturer_Part_Number=RC0603JR-070RL, Package=SB0603
SW1: library part MCD-01685, "8 positions, Side Actuated DIP switch, 1.27mm, SMT, height 4.1mm, piano type", Manufacturer=C&K, Manufacturer_Part_Number=TDP08H1SBD1
T1 T2 T7 T8 T9 T10 T11: library part MCD-01028, "N-channel 20 V, 0.025 O typ., 6 A STripFET™ V Power MOSFET in a PowerFLAT™ 2x2 package", Manufacturer=STMICROELECTRONICS, Manufacturer_Part_Number=STL6N2VH5, Package="PowerFLAT 2x2"
T3: library part MCD-01596, "Current Sense Transformer, 1:250 ratio, xx mohm / 20 ohms, 11mH, 10A", Manufacturer="WURTH ELEKTRONIK", Manufacturer_Part_Number=750317809
T4: library part MCD-01570, "Current Sense Transformer, 1:125 ratio, 6 mohm / 6.5 ohms, 3mH, 10A", Manufacturer="WURTH ELEKTRONIK", Manufacturer_Part_Number=749251125
T5 T6: library part MCD-00574, "Power MOSFET - P-Channel 30 V, 0.048 ? typ., 4 A STripFET H6 DeepGATE - SOT23-6L", Alternate_Manufacturer=STMICROELECTRONICS, Alternate_Manufacturer_Part_Number=STT7P2UH7, Manufacturer_Part_Number=STT4P3LLH6
TP1 TP2 TP3 TP4: library part MCD-01506, "Test Point trought hole 1mm/2mm", Manufacturer=n/a
U1: library part MCD-01066, "5 unidirectional Transil diodes ESD protection", Manufacturer=STMICROELECTRONICS, Manufacturer_Part_Number=ESDA6V1-5SC6, Package=SOT23-6L
U2 U7: library part MCD-00170, "ESD protection 6V1", Manufacturer=STMICROELECTRONICS, Manufacturer_Part_Number=ESDALC6V1-1U2
U3: library part MCD-01584, "STM32G474RET6U MCU, LQFP64 10x10, 1.6, 512KB Flash, 128KB SRAM", Manufacturer=STMICROELECTRONICS, Package="LQFP64 10x10 x 1.6"
U4: library part MCD-00215, "Low quiescent current and low noise voltage regulators", Manufacturer=STMICROELECTRONICS, Manufacturer_Part_Number=LD39050PU33R, Package="DFN6 3x3mm"
U5: library part MCD-00086, "Ultra low drop-low noise BiCMOS voltage, regulators low ESR capacitors compatible", Manufacturer=STMICROELECTRONICS, Manufacturer_Part_Number=LD3985M33R
U6: library part MCD-01593, "Integrated Circuit 40V, 1A Synchronous Buck-Boost DC/DC Converter with Programmable Output Current, -40°C to 150°C", Manufacturer="LINEAR TECHNOLOGY", Manufacturer_Part_Number=LTC3114HFE-1-TRPBF, Package="16-Lead Plastic TSSOP + exposed pad"
U8 U13: library part MCD-00136, "Dual Transil array for ESD protection", Manufacturer=STMICROELECTRONICS, Manufacturer_Part_Number=ESDALC6V1W5
U9: library part MCD-00596, "STM32F723IEK  (STM32F7) BGA176", Manufacturer=STMICROELECTRONICS, Manufacturer_Part_Number=STM32F723IEK6
U10: library part MCD-00159, "500mA, Enhanced single channel power switches with active high enable pin", Alternate_Manufacturer="TEXAS INSTRUMENTS", Alternate_Manufacturer_Part_Number=TPS2051C, Manufacturer=STMICROELECTRONICS, Manufacturer_Part_Number=STMPS2151STR
U11: library part MCD-00163, "Very low capacitance ESD protection", Manufacturer=STMICROELECTRONICS, Manufacturer_Part_Number=USBLC6-2SC6
U12: library part MCD-01207, "High power Transient voltage suppressor:25V/35A EOS and ESD transients protection.", Manufacturer=STMICROELECTRONICS, Manufacturer_Part_Number=ESDA25P35-1U1M, Package=QFN1610
U14: library part MCD-00251, "High power transient voltage suppressor, 7V breakdown", Manufacturer=STMICROELECTRONICS, Manufacturer_Part_Number=ESDA7P60-1U1M
U15: library part MCD-00649, "Common mode filter with ESD protection for USB 2.0 interface", Manufacturer=STMICROELECTRONICS, Manufacturer_Part_Number=ECMF02-2AMX6
U16: library part MCD-01192, "Single, dual, and quad rail to rail input/ouput 8Mhz operational amplifiers", Manufacturer=STMICROELECTRONICS, Manufacturer_Part_Number=TSV911ILT, Package=SOT23-5
U17: library part MCD-01157, "Programmable voltage reference", Manufacturer=STMICROELECTRONICS, Manufacturer_Part_Number=TL1431ACL5T, Package=SOT23-5L
U18: library part MCD-00255, "Dual Transil array ESD protection", Manufacturer=STMICROELECTRONICS, Manufacturer_Part_Number=ESDA6V1L
X1: library part MCD-00597, "Oscillator 25Mhz, +-50ppm, Vcc:3.3V typ, square wave: [0.1Vcc;0.9Vcc], Enable pin, SMD", Alternate_Manufacturer=NDK, Alternate_Manufacturer_Part_Number="NZ2520SB 25MHz END4869B", Manufacturer_Part_Number="NZ2520SH 25MHz END4869C"
X2: library part MCD-01036, "Crystal 24MHz, 6pF, +-20ppm, 80ohms max, SMD", Manufacturer=NDK, Manufacturer_Part_Number="NX2016SA 24MHz EXS00A-CS10820", Package="(2016) 2.0 x 1.6 x 0.45 mm"

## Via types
v1: diameter 0.45, hole 0.2, Top Layer to Bottom Layer, tented both sides, 1460 vias
v2: diameter 0.6, hole 0.2, Top Layer to Bottom Layer, tented both sides, 9 vias

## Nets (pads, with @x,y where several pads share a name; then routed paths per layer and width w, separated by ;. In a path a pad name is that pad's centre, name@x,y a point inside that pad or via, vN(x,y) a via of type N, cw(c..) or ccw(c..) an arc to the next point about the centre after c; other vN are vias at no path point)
1S: D1.2 R21.1 T3.1 T4.1 | length 3.5
  Top Layer w0.5: T3.1@12.675,10.575 12.545,10.445 D1.2@12.545,8.525 13.575,8.525 R21.1@13.825,8.775
3V3: C35.2 C36.2 CN1.3 JP4.1 R92.2 R127.2 SB22.1 SB30.1 U4.4 | length 68.4
  Top Layer w0.3: v1(31.085,115.282) v1@31.095,115.292
  Top Layer w0.45: 43.175,99.375 U4.4@43.175,100.35 43.975,100.35 C36.2@44.35,99.975 ; 46.6,99.3 46.6,98.625 46.675,98.55 47.725,98.55 47.725,99.225
  Top Layer w0.5: v1(23.005,142.6) R127.2@23.005,141.975 v1(23.63,141.975) ; v1@31.085,114.8 v1(31.085,115.282) ; v1@31.095,115.292 CN1.3@31.095,117.493 ; 42.56,97.79 JP4.1@43.93,97.79 ; 43.93,96.655 JP4.1@43.93,97.79 ; 43.93,99.195 JP4.1@43.93,97.79 ; 44.35,99.2 C36.2@44.35,99.975 44.425,99.9 C35.2@45.475,99.9 ; 46.6,98.625 45.765,97.79 JP4.1@43.93,97.79 ; SB22.1@35.564,90.679 35.8,90.915 v1(35.8,91.75) ; SB22.1@35.564,90.679 35.25,90.993 v1(35.25,91.75) v1(35.8,91.75) ; SB22.1@35.564,90.679 35.564,91.514 v1(35.8,91.75)
  Top Layer w0.6: 46.35,99.65 46.9,100.2 SB30.1@48.425,100.2 48.425,100.025 47.85,99.45
  Signal Layer 2 w0.5: 23.005,141.35 23.005,141.975 ; 23.005,141.35 v1(23.63,141.975) ; 23.005,141.35 22.975,141.32 22.975,140.55 23.5,140.025 23.5,129.4 26.675,126.225 26.675,118.65 30.043,115.282 ; 23.005,141.975 v1(23.005,142.6) v1(23.63,141.975) ; 23.005,141.975 v1(23.63,141.975) ; 30.043,115.282 30.393,115.282 ; 30.043,115.282 30.72,114.605 v1@31.07,114.605 ; 30.393,115.282 v1(31.085,115.282) 31.085,114.605 v1@31.07,114.605 ; 30.393,115.282 v1@31.07,114.605
  Signal Layer 2 w0.8: 42.425,97.8 JP4.1@43.93,97.8 ; JP4.1@43.93,97.79 JP4.1@43.93,97.8 ; 43.93,99.32 JP4.1@43.93,97.8 ; 45.575,97.8 JP4.1@43.93,97.8
  Bottom Layer w0.3: v1(23.005,142.6) 23.613,141.992 v1@23.613,141.975
  Bottom Layer w0.45: 35.564,91.804 35.564,92.279
  Bottom Layer w0.5: v1@31.085,114.605 v1(31.085,115.282)
  other v1: 36.925,99.5 36.5,99.925 36.075,100.375 36.925,100.375 34.225,100.575 33.8,100.825 34.275,101 31.1,114.8
3V3_OUT: CN8.1 SB30.2 | length 2.4
  Top Layer w0.6: SB30.2@49.525,100.2 49.525,97.795 CN8.1@49.53,97.79
3V3_STLK: C45.2 C47.2 C59.2 C60.2 C61.2 C62.2 C63.2 C64.2 C65.2 C66.2 C67.2 C70.2 C71.2 C72.2 C73.2 C75.2 C76.2 C77.2 C79.2 C80.2 C81.2 C83.2 CN4.1 LD9.4 R116.1 R123.1 U5.5 U9.C1 U9.C5 U9.C7 U9.C8 U9.C9 U9.F3 U9.G3 U9.G13 U9.H13 U9.J12 U9.J13 U9.K4 U9.N8 U9.N9 U9.N10 U9.P1 U9.R1 X1.4 | length 104
  Top Layer w0.15: 31.53,138.4 31.785,138.145 33.1,138.145 U9.C8@33.43,138.475 ; 31.63,136.025 31.805,136.2 33.105,136.2 U9.C5@33.43,136.525 ; 31.63,139.025 31.855,138.8 33.105,138.8 U9.C9@33.43,139.125 ; 31.705,137.425 31.785,137.505 33.11,137.505 U9.C7@33.43,137.825 ; 34.255,133.425 34.41,133.58 34.41,134.708 34.597,134.895 35.05,134.895 U9.F3@35.38,135.225 ; U9.G3@36.03,135.225 36.35,134.905 36.825,134.905 37.005,134.725 37.005,133.65 37.18,133.475 ; U9.J12@37.33,141.075 37.65,141.395 38.753,141.395 38.96,141.602 38.96,143.305 39.155,143.5 ; U9.K4@37.98,135.875 37.66,135.555 37.66,134.442 37.857,134.245 38.763,134.245 38.955,134.053 38.955,133.475 ; U9.N8@39.93,138.475 40.25,138.155 41.725,138.155 ; U9.N9@39.93,139.125 40.255,138.8 41.73,138.8 ; U9.N10@39.93,139.775 40.255,139.45 41.705,139.45
  Top Layer w0.16: 33.755,143.275 33.755,143.16 33.755,142.85 33.905,142.7 35.48,142.7 ; 35.515,142.7 35.605,142.7 35.705,142.6 35.705,142.24 35.705,142.05 U9.G13@36.03,141.725 ; 36.08,143.45 36.355,143.175 36.355,142.05 U9.H13@36.68,141.725 ; 36.805,143.575 37.005,143.375 37.005,142.05 U9.J13@37.33,141.725
  Top Layer w0.25: U9.P1@40.58,133.925 40.58,133.45 41.155,132.875 C66.2@41.155,132.4 ; U9.R1@41.23,133.925 41.23,133.575 C67.2@42.405,132.4
  Top Layer w0.3: v1(29.08,135.975) R123.1@29.705,135.975 ; v1(30.155,134.4) 30.605,134.85 C70.2@30.605,135 31.155,135 31.43,135.275 31.43,135.825 31.63,136.025 ; v1(30.155,136.7) 30.605,137.15 C72.2@30.605,137.3 31.58,137.3 31.705,137.425 ; v1(30.155,138.3) 30.605,138.75 C75.2@30.605,138.9 31.03,138.9 31.53,138.4 ; v1(30.155,139.55) C77.2@30.605,140 ; C60.2@30.33,132.325 v1(30.33,132.975) ; C77.2@30.655,140 C77.2@30.605,140 ; 31.63,139.025 31.205,139.45 31.205,139.925 30.98,140.15 C77.2@30.605,140.15 C77.2@30.605,140 ; C61.2@31.68,132.325 v1(31.68,132.975) ; v1(31.68,144.55) C79.2@32.33,144.55 32.33,143.7 32.605,143.425 33.605,143.425 33.755,143.275 ; C62.2@32.805,132.4 32.805,132.9 33.43,133.525 U9.C1@33.43,133.925 ; C62.2@32.955,132.4 v1(33.405,131.95) ; v1(34.03,145) 34.48,144.55 C80.2@34.63,144.55 ; C63.2@34.055,132.4 34.055,133.225 34.255,133.425 ; C63.2@34.205,132.4 v1(34.655,131.95) ; C80.2@34.63,144.525 34.68,144.525 35.355,143.85 35.68,143.85 36.08,143.45 ; v1(34.855,128) C59.2@34.855,128.625 X1.4@36.03,128.625 ; v1(35.28,145) 35.73,144.55 C81.2@35.88,144.55 35.88,144.475 36.78,143.575 ; 37.18,133.475 37.605,133.05 C64.2@37.605,132.4 37.755,132.4 v1(38.205,131.95) ; R116.1@38.53,129.525 v1(39.255,129.525) ; 38.955,133.475 38.855,133.375 C65.2@38.855,132.4 39.005,132.4 v1(39.455,131.95) ; v1(39.03,145) C83.2@39.48,144.55 ; 39.155,143.5 39.63,143.975 39.63,144.4 C83.2@39.48,144.55 ; C83.2@39.63,144.55 C83.2@39.48,144.55 ; C66.2@41.155,132.4 41.305,132.4 v1(41.755,131.95) ; 41.705,139.45 42.705,139.45 C76.2@42.755,139.5 42.755,139.35 v1(43.205,138.9) ; 41.725,138.155 42.755,137.125 C71.2@42.755,137 42.755,136.85 v1(43.205,136.4) ; 41.73,138.8 42.205,138.8 C73.2@42.755,138.25 42.755,138.1 v1(43.205,137.65) ; C67.2@42.405,132.4 42.555,132.4 v1(43.005,131.95) ; LD9.4@47.99,141.93 v1(47.99,140.87) v1@48.575,140.87 ; v1(48.575,140.865) v1@48.575,140.87 ; LD9.4@48.575,141.925 v1@48.575,140.87 ; LD9.4@49.165,141.93 v1(49.165,140.87) v1@48.575,140.87
  Top Layer w0.5: C45.2@33.45,109.625 33.45,109.85 34.025,110.425 ; C47.2@33.45,110.75 33.775,110.425 34.025,110.425 ; C47.2@33.45,110.75 33.925,110.75 34.625,111.45 v1(34.625,111.625) ; C47.2@33.45,110.75 33.45,110.89 34.185,111.625 v1(34.625,111.625) ; 34.025,110.425 v1(35.225,111.625) v1(34.625,111.625)
  Top Layer w0.8: U5.5@31.975,108.325 31.975,108.95 32.65,109.625 ; C45.2@33.45,109.625 32.65,109.625 ; C45.2@33.45,109.85 C47.2@33.45,110.425 ; C47.2@33.45,110.75 C47.2@33.45,110.425 ; 32.65,109.625 C47.2@33.45,110.425
  Signal Layer 2 w0.5: v1(31.68,132.975) 32.21,132.445 32.21,130.629 32.31,130.529 32.31,130.242 33.229,129.323 33.229,129.32 32.88,128.971 32.88,128.479 33.229,128.13 33.721,128.13 34.07,128.479 34.07,128.482 ; 34.07,128.93 34.07,128.482 ; 35.185,127.029 34.885,127.329 34.885,127.766 34.478,128.173 34.379,128.173 34.07,128.482
  Bottom Layer w0.5: v1(34.625,111.625) v1(35.225,111.625) ; v1(47.99,140.87) v1(49.165,140.87)
5V: C39.2 C40.2 JP5.2 JP5.4 JP5.6 JP5.8 Q11.3 R104.2 R125.1 R133.1 R137.2 SB38.1 U4.1 U4.6 | length 116.4
  Top Layer w0.12: R125.1@20.905,141.975 20.905,142.58 21.475,143.15 24.565,143.15 v1(24.81,142.905)
  Top Layer w0.2: JP5.8@46.99,113.03 46.99,114.025 ; R104.2@46.99,114.89 47,114.9 R104.2@47,115.275
  Top Layer w0.45: U4.1@40.575,102.25 40.575,102.85 41.375,103.65 C40.2@44.15,103.65 C39.2@44.15,102.525 43.875,102.25 U4.6@43.175,102.25 43.175,103.125
  Top Layer w0.5: 44.71,105.41 45.675,105.41 ; JP5.2@46.975,105.41 JP5.2@46.99,105.41 48.14,105.41 ; JP5.4@46.99,107.95 48.155,107.95 ; JP5.6@46.99,110.49 48.155,110.49 ; 46.99,114.025 R104.2@46.99,114.89 ; JP5.8@47,113.04 JP5.8@46.99,113.03 48.155,113.03
  Top Layer w0.8: 45.4,107.95 JP5.4@46.975,107.95 ; 45.675,105.41 JP5.2@46.975,105.41 ; 46.975,104.05 JP5.2@46.975,105.41 ; JP5.4@46.99,107.95 JP5.4@46.975,107.95 ; JP5.8@46.99,113.03 JP5.8@46.975,113.03 ; 46.99,114.025 46.975,114.01 JP5.8@46.975,113.03 ; JP5.2@46.975,105.41 JP5.4@46.975,107.95 ; JP5.4@46.975,107.95 JP5.6@46.975,110.49 ; JP5.6@46.975,110.49 46.965,110.5 45.075,110.5 45.175,110.6 45.175,112.96 45.245,113.03 JP5.8@46.975,113.03 ; JP5.6@46.975,110.49 JP5.8@46.975,113.03
  Signal Layer 2 w0.5: v1(24.81,142.905) 25.115,142.6 27.875,142.6 28.675,141.8 28.675,140.586 28.225,140.136 28.225,131.125 34.35,125 34.35,119.225 36.225,117.35 40.25,117.35 v1(40.975,116.625)
  Bottom Layer w0.3: 34.5,64.85 34.5,64.675 33.925,64.1 33.925,63.1 34.75,62.275 34.925,62.275
  Bottom Layer w0.5: 38.95,81.3 43.65,81.3 44.125,81.775 Q11.3@44.125,83.5 R137.2@46.525,83.5 ; v1(40.975,116.625) 43.025,116.625 43.05,116.6 ; 43.075,116.625 43.05,116.6 ; 43.55,114.3 43.05,114.8 43.05,116.6 ; JP5.2@46.99,105.41 48.14,105.41 ; JP5.4@46.99,107.95 48.155,107.95 ; JP5.6@46.99,110.49 48.145,110.49 ; JP5.8@47,113.04 JP5.8@46.99,113.03 48.15,113.03
  Bottom Layer w0.8: 45.175,113.05 45.195,113.03 JP5.8@46.975,113.03 ; 45.275,110.525 45.31,110.49 JP5.6@46.975,110.49 ; 45.375,105.375 45.41,105.41 JP5.2@46.975,105.41 ; 45.525,107.975 45.55,107.95 JP5.4@46.975,107.95 ; 46.975,103.875 JP5.2@46.975,105.41 ; 46.975,114.7 JP5.8@46.975,113.03 ; JP5.2@46.99,105.41 JP5.2@46.975,105.41 ; JP5.4@46.99,107.95 JP5.4@46.975,107.95 ; JP5.6@46.99,110.49 JP5.6@46.975,110.49 ; JP5.8@46.99,113.03 JP5.8@46.975,113.03 ; JP5.2@46.975,105.41 JP5.4@46.975,107.95 ; JP5.4@46.975,107.95 JP5.6@46.975,110.49 ; JP5.6@46.975,110.49 JP5.8@46.975,113.03
5V_OUT: C97.2 C98.2 C99.2 CN9.3 SB38.2 | length 25.1
  Top Layer w0.45: v1(36.25,101.6) v1(36.75,101.6) v1(37.25,101.6)
  Signal Layer 2 w0.3: 4.95,91.475 7.225,91.475 7.25,91.5
  Signal Layer 2 w0.45: 32.16,103.405 33.965,101.6 v1(36.25,101.6) v1(36.75,101.6) v1(37.25,101.6)
  Signal Layer 2 w0.8: 4.91,92.71 CN9.3@6.35,92.71 ; 6.35,91.732 CN9.3@6.35,92.71 ; 6.35,93.7 CN9.3@6.35,92.71 ; 7.625,92.725 7.61,92.71 CN9.3@6.35,92.71
  Bottom Layer w0.3: v1(36.25,101.6) 36.25,101.975 SB38.2@36.775,102.5 ; v1(36.75,101.6) 36.775,101.625 36.775,101.9 SB38.2@36.775,102.5 ; v1(37.25,101.6) 37.25,102.025 SB38.2@36.775,102.5
  Bottom Layer w0.4: CN9.3@6.35,92.71 7.76,92.71 C97.2@8.6,93.55 ; v1(21.725,103.85) v1(22.475,103.85) 22.775,103.85 C98.2@23.45,103.85
  Bottom Layer w0.45: v1(36.75,101.6) v1(36.25,101.6) 36.55,101.9 36.775,101.9 36.95,101.9 v1(37.25,101.6) 36.8,101.6 v1@36.775,101.625 ; SB38.2@36.775,102.5 36.775,102.925 37.275,103.425 C99.2@37.275,103.85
